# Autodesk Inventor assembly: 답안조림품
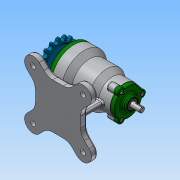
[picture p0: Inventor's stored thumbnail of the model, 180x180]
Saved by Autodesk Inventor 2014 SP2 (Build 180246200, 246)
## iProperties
Created: 2017-03
Part Number: 답안조림품
Document SubType Name: Assembly
Designer: SDA
Author: SDA
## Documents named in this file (14)
- C:\Users\SDA\Desktop\470307V1002\답안조림품.iam
- C:\Users\SDA\Desktop\470307V1002\1.본체.ipt
- C:\Users\SDA\Desktop\470307V1002\뒤커버.ipt
- C:\Users\SDA\Desktop\470307V1002\앞커버.ipt
- C:\Users\SDA\Desktop\470307V1002\오일 실 10 20 7.ipt
- C:\Users\SDA\Desktop\470307V1002\오일 실 17 30 8.ipt
- C:\Users\SDA\Desktop\470307V1002\베어링-6200.ipt
- C:\Users\SDA\Desktop\470307V1002\베어링-6203.ipt
- C:\Users\SDA\Desktop\470307V1002\축.ipt
- C:\Users\SDA\Desktop\470307V1002\키5x5.ipt
- C:\Users\SDA\Desktop\470307V1002\스프로킷.ipt
- C:\Users\SDA\Desktop\470307V1002\볼트 M4 x 12.ipt
- C:\Users\SDA\Desktop\470307V1002\볼트 M5 x 10.ipt
- 볼트 M5 x 10.ipt
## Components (10 placed, 2 different names)
1. 1.본체:1
2. ISO 4762 M4 x 12:1
3. ISO 4762 M4 x 12:3
4. ISO 4762 M4 x 12:4
5. ISO 4762 M4 x 12:2
6. ISO 4762 M4 x 12:5
7. ISO 4762 M4 x 12:6
8. ISO 4762 M4 x 12:7
9. ISO 4762 M4 x 12:8
10. ISO 4762 M4 x 12:9
